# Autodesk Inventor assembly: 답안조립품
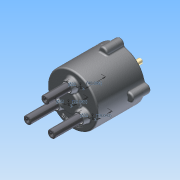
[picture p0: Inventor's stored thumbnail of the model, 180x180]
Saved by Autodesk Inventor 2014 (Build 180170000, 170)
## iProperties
Created: 2015-09
Part Number: 답안조립품
Document SubType Name: Assembly
Designer: study
Mass: 2160.25 g
Surface Area: 1801.24 cm^2
Volume: 438.523 cm^3
Density: 4.9262 g/cm^3
Author: study
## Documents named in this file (14)
- C:\Users\study\Desktop\350916V1017\답안조립품.iam
- C:\Users\study\Desktop\350916V1017\몸체.ipt
- C:\Users\study\Desktop\350916V1017\베어링 NA 4900.ipt
- C:\Users\study\Desktop\350916V1017\메인 축.ipt
- C:\Users\study\Desktop\350916V1017\멈춤링 10 x 1.ipt
- C:\Users\study\Desktop\350916V1017\커버.ipt
- C:\Users\study\Desktop\350916V1017\멈춤링 22 x 1.2.ipt
- C:\Users\study\Desktop\350916V1017\판캠.ipt
- C:\Users\study\Desktop\350916V1017\M5x0.8x20.ipt
- C:\Users\study\Desktop\350916V1017\오일실.ipt
- C:\Users\study\Desktop\350916V1017\슬라이드 축.ipt
- C:\Users\study\Desktop\350916V1017\가변스프링-01.ipt
- C:\Users\study\Desktop\350916V1017\가변스프링-02.ipt
- C:\Users\study\Desktop\350916V1017\가변스프링-03.ipt
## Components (7 placed, 4 different names)
1. 가변스프링-01:1
2. 가변스프링-02:1
3. 가변스프링-03:1
4. M5x0.8x20:1
5. M5x0.8x20:2
6. M5x0.8x20:3
7. M5x0.8x20:4
